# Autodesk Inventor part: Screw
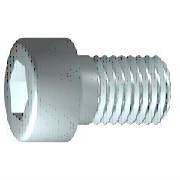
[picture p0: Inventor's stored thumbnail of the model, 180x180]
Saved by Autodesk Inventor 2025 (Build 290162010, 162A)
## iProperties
Created: 2005-10
Part Number: Screw
Material: Stainless Steel
Description: 六角承窩頭螺釘
Vendor: Autodesk Inc.
Document SubType Name: Modeling
Standard: ISO 4762
Designer: Power User
Standards Organization: ISO
Language: zh-TW
Size Designation: M10 x 40
Categories: <MemberInstance Version="R10.0.0"><Categories><Category DisplayName="結件" InternalName="e4da775c-781d-43d5-af7c-5136215cf5a6" Mnemonic="FSTN"><Category DisplayNa
Mass: 38.3534 g
Surface Area: 22.7501 cm^2
Volume: 4.79417 cm^3
Density: 8 g/cm^3
Appearance: Semi-Polished
Author: Power User
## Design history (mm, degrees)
sketch "草圖1"
  geometry: L1 (-2.333, 0)-(40, 0); L2 (40, 0)-(40, 5); L3 (40, 5)-(3.75, 5); L4 (3.75, 5)-(2.83, 5); L5 (2.83, 5)-(0, 5); L6 (0, 5)-(0, 8); L7 (0, 8)-(-10, 8); L8 (-10, 8)-(-10, 4.619); L9 (-10, 4.619)-(-5, 4.619); L10 (-5, 4.619)-(-2.333, 0); L11 (-15, 0)-(55, 0) reference; L12 (0, -0.8)-(0, 10.4) reference; L13 (3.75, 5)-(0, 5)
  constraints: 22 end point, 6 parallel, 2 collinear, 2 perpendicular, 1 horizontal, 1 point on line
  dimensions: "d1" = 36.25 distance from line of L3.end L2 (= GEL); "d2" = 0.92028 distance of L4.end L3.end (computed from GAL); "d3" = 10 distance between parallel lines of L8 L6 (= KOH); "d4" = 5 distance of L8.end L9.end (= INTI); "d5" = 60 deg angle of L10 L1; "d6" = 10 diameter of L3 L1 (= GD); "d7" = 10 diameter of L5 L1 (= BDM); "d8" = 9.2376 diameter of L9 L1 (= 1.1547 x SW); "d9" = 16 diameter of L7 L1 (= KOD); "d26" = 40 distance between parallel lines of L12 L2 (= NLG)
revolve "本體" sketch "草圖1" stored, may be unused: angle "d10" = 90 deg
sketch "草圖2"
  geometry: L1 (0, -9.6)-(0, 12.8) reference; L2 (-9.6, 0)-(12.8, 0) reference; L3 (4.619, 0)-(2.309, -4); L4 (2.309, -4)-(-2.309, -4); L5 (-2.309, -4)-(-4.619, 0); L6 (-4.619, 0)-(-2.309, 4); L7 (-2.309, 4)-(2.309, 4); L8 (2.309, 4)-(4.619, 0); 2 further points
  constraints: 12 end point, 1 coincident, 1 horizontal alignment, 1 point on line, 12 other
extrude "槽" join sketch "草圖2" stored distance "d11" = 10; taper "d12" = 0 deg
chamfer "去角1" distance "d15" = 0.92018 (= -0.5 x SPD + 0.5 x GD); stored, may be unused: second distance "d16" = 0.92018 (= GUL), angle "d27" = 45 deg
node "實體1"
node "實體本體"
node "曲面本體"
fillet "圓角1" dims "d17" = 1 (= RR)
feature "螺紋" dims "d13" = 36.25 (= GEL), "d14" = 0
other parameters: "GD" = 10 [user parameter; used in 2 equation terms], "NLG" = 40 [user parameter; used in 1 equation term], "GEL" = 36.25 [user parameter; used in 2 equation terms], "KOD" = 16 [user parameter; used in 1 equation term], "KOH" = 10 [user parameter; used in 1 equation term], "INTI" = 5 [user parameter; used in 1 equation term], "GAL" = 0.92018 (= 0.61345 x PTC) [user parameter; used in 1 equation term], "GUL" = 0.92018 (= 0.61345 x PTC) [user parameter; used in 1 equation term], "BDM" = 10 (= NND) [user parameter; used in 1 equation term], "SW" = 8 [user parameter; used in 2 equation terms], "RR" = 1 [user parameter; used in 1 equation term], "SPD" = 8.15965 (= NND - 1.2269 x PTC) [user parameter; used in 1 equation term], "E0" = 9.24 (= 1.155 x SW) [user parameter], "FAWI" = 45 deg [user parameter], "TPU" = 6.66667 (computed from PTC) [user parameter], "GD1" = 8.15965 (= THREADDIA - 1.2269 x PTC) [user parameter], "PTC" = 1.5 [user parameter; used in 5 equation terms], "TOA" = 30 deg [user parameter], "d29" = 0
